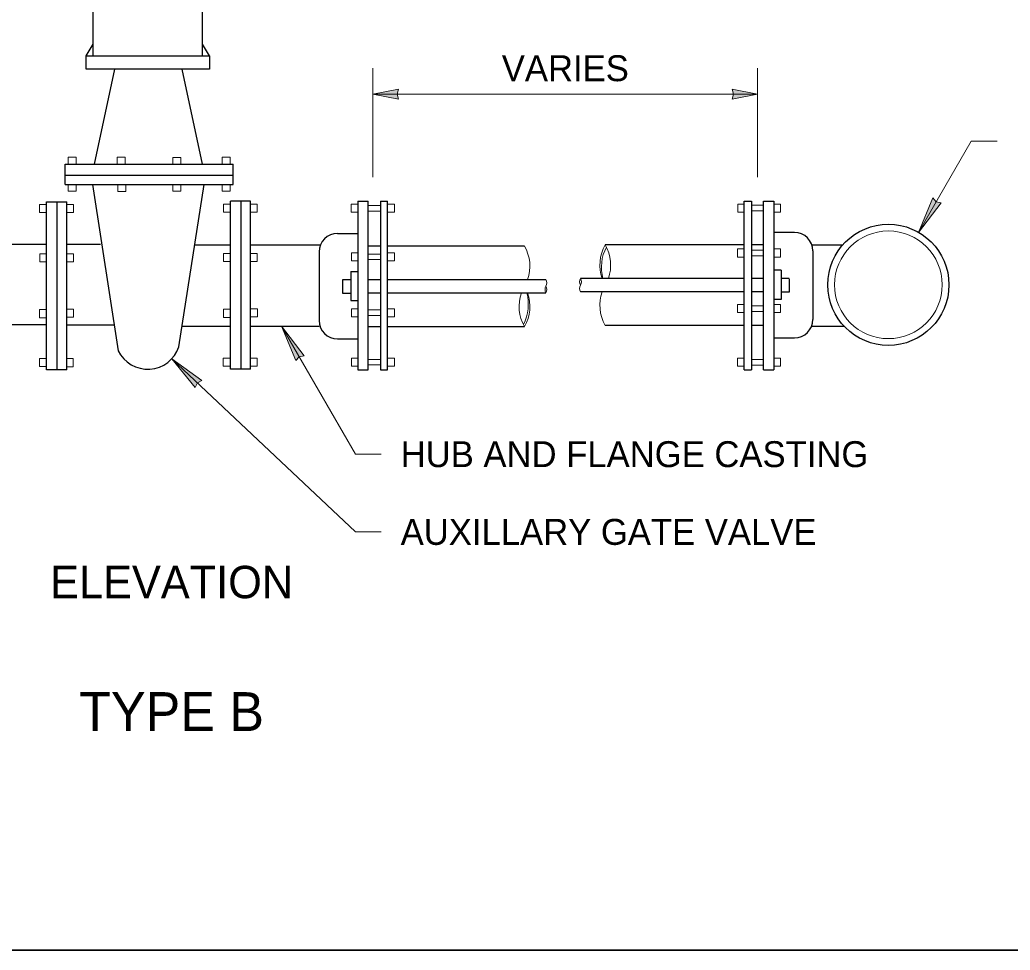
# Model space of a CAD drawing. Extents: x 99860 to 103153, y 99998 to 102077.
# Drawn here: x 101906 to 102518, y 100000 to 100574 of the extents above; entities that cross this region are included whole.
import ezdxf
from ezdxf.enums import TextEntityAlignment as Align

# ---------------------------------------------------------------- set-up
doc = ezdxf.new("R2010")
doc.units = 0
doc.header["$LTSCALE"] = 6.4
for name, color, linetype, lineweight in [('1', 7, 'Continuous', 25), ('15', 7, 'Continuous', 13), ('18', 7, 'Continuous', 13), ('20', 7, 'Continuous', 13), ('6', 7, 'Continuous', 25)]:
    doc.layers.add(name, color=color, linetype=linetype, lineweight=lineweight)

msp = doc.modelspace()

# ---------------------------------------------------------------- hatches: boundary and pattern name
at = {"layer": '15'}
for points in [[(102124.052, 100528.071), (102139.777, 100524.987), (102139.049, 100528.071), (102139.777, 100531.155)], [(102361.677, 100528.071), (102345.952, 100524.987), (102346.68, 100528.071), (102345.952, 100531.155)], [(102461.132, 100442.715), (102475.131, 100460.993), (102472.017, 100461.569), (102469.961, 100463.978)], [(102067.564, 100384.76), (102081.563, 100366.482), (102078.449, 100365.906), (102076.393, 100363.497)]]:
    msp.add_hatch(color=256, dxfattribs=at).paths.add_polyline_path(points)
at = {"layer": '20'}
msp.add_hatch(color=256, dxfattribs=at).paths.add_polyline_path([(101999.71, 100364.654), (102014.28, 100346.827), (102015.558, 100349.724), (102018.374, 100351.172)])

# ---------------------------------------------------------------- linework, layer by layer
at = {"layer": '1'}
msp.add_line((102018.714, 100484.735), (102006.202, 100543.535), dxfattribs=at)
at = {"layer": '1', "lineweight": 35}
msp.add_lwpolyline([(99862, 99999.5), (103151, 99999.5), (103151, 102075.5), (99862, 102075.5)], close=True, dxfattribs=at)
at = {"layer": '15'}
for p, q in [((102124.052, 100476.885), (102124.052, 100544.015)), ((102361.677, 100476.885), (102361.677, 100544.015)), ((102361.677, 100528.071), (102124.052, 100528.071)), ((102461.132, 100442.715), (102493.633, 100499.007)), ((102493.633, 100499.007), (102509.632, 100499.007)), ((102067.564, 100384.76), (102113.17, 100305.769)), ((102113.17, 100305.769), (102129.17, 100305.769)), ((102113.17, 100257.769), (102129.17, 100257.769))]:
    msp.add_line(p, q, dxfattribs=at)
for points in [[(102124.052, 100528.071), (102139.777, 100524.987), (102139.049, 100528.071), (102139.777, 100531.155)], [(102361.677, 100528.071), (102345.952, 100524.987), (102346.68, 100528.071), (102345.952, 100531.155)], [(102461.132, 100442.715), (102475.131, 100460.993), (102472.017, 100461.569), (102469.961, 100463.978)], [(102067.564, 100384.76), (102081.563, 100366.482), (102078.449, 100365.906), (102076.393, 100363.497)]]:
    msp.add_lwpolyline(points, close=True, dxfattribs=at)
at = {"layer": '18', "lineweight": 25}
for p, q in [((101951.214, 100551.772), (101951.214, 100607.085)), ((102018.777, 100551.772), (102018.777, 100607.085)), ((101946.964, 100551.772), (101951.214, 100558.985)), ((102023.039, 100551.772), (102018.777, 100558.985)), ((101952.052, 100484.735), (101964.577, 100543.535)), ((101933.914, 100484.735), (102037.652, 100484.735)), ((101933.914, 100472.247), (101933.914, 100484.735)), ((102037.652, 100472.247), (102037.652, 100484.735)), ((101933.914, 100478.097), (102037.652, 100478.097)), ((101933.914, 100472.247), (102037.652, 100472.247)), ((101950.727, 100472.247), (101966.664, 100369.622)), ((102004.139, 100372.022), (102019.677, 100472.247)), ((102035.952, 100358.147), (102035.952, 100461.885)), ((102048.452, 100461.885), (102035.952, 100461.885)), ((102042.589, 100358.147), (102042.589, 100461.885)), ((102048.452, 100358.147), (102048.452, 100461.885)), ((102114.777, 100461.885), (102114.777, 100357.772)), ((102114.777, 100461.885), (102121.152, 100461.885)), ((102121.152, 100357.935), (102121.152, 100461.885)), ((102128.614, 100461.885), (102128.614, 100357.935)), ((102128.614, 100461.885), (102133.127, 100461.885)), ((102133.127, 100357.935), (102133.127, 100461.885)), ((102353.389, 100357.935), (102353.389, 100461.885)), ((102353.389, 100461.885), (102357.889, 100461.885)), ((102357.889, 100461.885), (102357.889, 100357.935)), ((102365.352, 100357.935), (102365.352, 100461.885)), ((102365.352, 100461.885), (102371.739, 100461.885)), ((102371.739, 100461.885), (102371.739, 100357.935)), ((101922.389, 100357.935), (101922.389, 100461.66)), ((101922.389, 100461.66), (101934.877, 100461.66)), ((101929.014, 100357.935), (101929.014, 100461.66)), ((101934.877, 100357.935), (101934.877, 100461.66)), ((101897.077, 100435.397), (101922.389, 100435.397)), ((101934.877, 100435.397), (101955.752, 100435.397)), ((102013.906, 100435.022), (102035.952, 100435.022)), ((102376.202, 100419.297), (102371.739, 100419.297)), ((102376.202, 100419.297), (102376.202, 100401.322)), ((102105.277, 100413.585), (102110.302, 100413.585)), ((102105.277, 100413.41), (102105.277, 100405.147)), ((102110.302, 100418.647), (102110.302, 100400.672)), ((102110.302, 100418.647), (102114.777, 100418.647)), ((102121.152, 100413.585), (102128.614, 100413.585)), ((102133.127, 100413.585), (102230.907, 100413.585)), ((102353.389, 100414.21), (102252.233, 100414.21)), ((102365.352, 100414.21), (102357.889, 100414.21)), ((102381.227, 100414.21), (102376.202, 100414.21)), ((102381.227, 100414.047), (102381.227, 100405.785)), ((102105.277, 100405.147), (102110.302, 100405.147)), ((102110.302, 100400.672), (102114.777, 100400.672)), ((102121.152, 100405.36), (102128.614, 100405.36)), ((102133.127, 100405.36), (102230.908, 100405.36)), ((102353.389, 100406.01), (102252.219, 100406.01)), ((102365.352, 100406.01), (102357.889, 100406.01)), ((102376.202, 100401.322), (102371.739, 100401.322)), ((102381.227, 100405.785), (102376.202, 100405.785)), ((101922.389, 100385.622), (101826.888, 100385.622)), ((101934.877, 100385.622), (101964.18, 100385.622)), ((102006.114, 100384.76), (102035.952, 100384.76)), ((101934.877, 100357.935), (101922.389, 100357.935)), ((102048.452, 100358.147), (102035.952, 100358.147)), ((102353.389, 100357.935), (102357.889, 100357.935)), ((102365.352, 100357.935), (102371.739, 100357.935)), ((102114.777, 100357.772), (102121.152, 100357.772)), ((102128.614, 100357.772), (102133.127, 100357.772))]:
    msp.add_line(p, q, dxfattribs=at)
at = {"layer": '18'}
for p, q in [((101935.827, 100489.135), (101940.802, 100489.135)), ((101935.827, 100484.735), (101935.827, 100489.135)), ((101940.802, 100484.735), (101940.802, 100489.135)), ((101966.027, 100489.047), (101970.989, 100489.047)), ((101966.027, 100484.735), (101966.027, 100489.047)), ((101970.989, 100484.735), (101970.989, 100489.047)), ((102000.439, 100488.922), (102005.402, 100488.922)), ((102000.439, 100484.822), (102000.439, 100488.922)), ((102005.402, 100484.735), (102005.402, 100488.922)), ((102030.927, 100484.735), (102030.927, 100489.047)), ((102030.927, 100489.047), (102035.902, 100489.047)), ((102035.902, 100484.735), (102035.902, 100489.047)), ((101935.764, 100472.247), (101935.764, 100468.172)), ((101935.764, 100468.172), (101940.739, 100468.172)), ((101940.739, 100472.247), (101940.739, 100468.172)), ((101966.389, 100472.247), (101966.389, 100468.022)), ((101966.389, 100468.022), (101971.352, 100468.022)), ((101971.352, 100472.247), (101971.352, 100468.022)), ((102000.439, 100472.247), (102000.439, 100468.135)), ((102000.439, 100468.135), (102005.402, 100468.135)), ((102005.402, 100472.247), (102005.402, 100468.135)), ((102030.927, 100472.247), (102030.927, 100468.11)), ((102030.927, 100468.11), (102035.902, 100468.11)), ((102035.902, 100472.247), (102035.902, 100468.11)), ((101922.389, 100459.91), (101918.064, 100459.91)), ((101918.064, 100454.947), (101918.064, 100459.91)), ((101934.877, 100459.91), (101939.014, 100459.91)), ((101939.014, 100454.947), (101939.014, 100459.91)), ((102035.952, 100460.122), (102031.639, 100460.122)), ((102031.639, 100455.16), (102031.639, 100460.122)), ((102048.452, 100460.122), (102052.577, 100460.122)), ((102052.577, 100455.16), (102052.577, 100460.122)), ((102110.677, 100455.097), (102110.677, 100460.06)), ((102114.777, 100460.06), (102110.677, 100460.06)), ((102128.614, 100459.347), (102121.152, 100459.347)), ((102121.152, 100455.835), (102128.614, 100455.835)), ((102133.277, 100460.06), (102137.377, 100460.06)), ((102137.377, 100455.097), (102137.377, 100460.06)), ((102353.389, 100460.16), (102349.352, 100460.16)), ((102349.352, 100455.185), (102349.352, 100460.16)), ((102365.352, 100459.447), (102357.889, 100459.447)), ((102357.889, 100455.935), (102365.352, 100455.935)), ((102371.739, 100460.16), (102375.777, 100460.16)), ((102375.777, 100455.185), (102375.777, 100460.16)), ((101922.389, 100454.947), (101918.064, 100454.947)), ((101934.877, 100454.947), (101939.014, 100454.947)), ((102035.952, 100455.16), (102031.639, 100455.16)), ((102048.452, 100455.16), (102052.577, 100455.16)), ((102110.677, 100455.097), (102114.777, 100455.097)), ((102137.377, 100455.097), (102133.277, 100455.097)), ((102349.352, 100455.185), (102353.389, 100455.185)), ((102375.777, 100455.185), (102371.739, 100455.185)), ((102349.314, 100432.46), (102353.389, 100432.46)), ((102349.314, 100427.497), (102349.314, 100432.46)), ((102357.889, 100431.747), (102365.352, 100431.747)), ((102375.739, 100432.46), (102371.739, 100432.46)), ((102375.739, 100427.497), (102375.739, 100432.46)), ((101918.189, 100424.447), (101918.189, 100429.41)), ((101922.389, 100429.41), (101918.189, 100429.41)), ((101934.877, 100429.41), (101938.977, 100429.41)), ((101938.977, 100424.447), (101938.977, 100429.41)), ((102031.764, 100424.66), (102031.764, 100429.622)), ((102035.952, 100429.622), (102031.764, 100429.622)), ((102048.452, 100429.622), (102052.552, 100429.622)), ((102052.552, 100424.66), (102052.552, 100429.622)), ((102110.739, 100425.097), (102110.739, 100430.06)), ((102110.739, 100430.06), (102114.777, 100430.06)), ((102121.152, 100429.347), (102128.614, 100429.347)), ((102121.152, 100425.86), (102128.614, 100425.86)), ((102137.377, 100430.06), (102133.277, 100430.06)), ((102137.377, 100425.097), (102137.377, 100430.06)), ((102349.314, 100427.497), (102353.389, 100427.497)), ((102357.889, 100428.272), (102365.352, 100428.272)), ((102375.739, 100427.497), (102371.739, 100427.497)), ((101922.289, 100424.447), (101918.189, 100424.447)), ((101934.877, 100424.447), (101938.977, 100424.447)), ((102035.864, 100424.66), (102031.764, 100424.66)), ((102048.452, 100424.66), (102052.552, 100424.66)), ((102110.739, 100425.097), (102114.777, 100425.097)), ((102137.377, 100425.097), (102133.277, 100425.097)), ((101918.064, 100390.035), (101918.064, 100394.997)), ((101922.389, 100394.997), (101918.064, 100394.997)), ((101934.877, 100395.372), (101939.102, 100395.372)), ((101939.102, 100390.397), (101939.102, 100395.372)), ((102031.639, 100390.247), (102031.639, 100395.21)), ((102035.952, 100395.21), (102031.639, 100395.21)), ((102048.452, 100395.585), (102052.677, 100395.585)), ((102052.677, 100390.622), (102052.677, 100395.585)), ((102110.739, 100390.56), (102110.739, 100395.522)), ((102114.777, 100395.522), (102110.739, 100395.522)), ((102128.614, 100394.81), (102121.152, 100394.81)), ((102133.127, 100395.522), (102137.414, 100395.522)), ((102137.414, 100390.56), (102137.414, 100395.522)), ((102353.389, 100398.11), (102349.252, 100398.11)), ((102349.252, 100393.147), (102349.252, 100398.11)), ((102365.352, 100397.397), (102357.889, 100397.397)), ((102371.739, 100398.11), (102375.739, 100398.11)), ((102375.739, 100393.147), (102375.739, 100398.11)), ((101922.389, 100390.035), (101918.064, 100390.035)), ((101934.877, 100390.397), (101939.102, 100390.397)), ((102035.952, 100390.247), (102031.639, 100390.247)), ((102048.452, 100390.622), (102052.677, 100390.622)), ((102110.739, 100390.56), (102114.777, 100390.56)), ((102121.152, 100391.297), (102128.614, 100391.297)), ((102137.414, 100390.56), (102133.127, 100390.56)), ((102349.252, 100393.147), (102353.389, 100393.147)), ((102357.889, 100393.885), (102365.352, 100393.885)), ((102375.739, 100393.147), (102371.739, 100393.147)), ((101917.977, 100359.847), (101917.977, 100364.81)), ((101922.389, 100364.81), (101917.977, 100364.81)), ((101934.877, 100364.747), (101938.952, 100364.747)), ((101938.952, 100359.785), (101938.952, 100364.747)), ((102031.552, 100360.06), (102031.552, 100365.022)), ((102035.952, 100365.022), (102031.552, 100365.022)), ((102048.452, 100364.96), (102052.514, 100364.96)), ((102052.514, 100359.997), (102052.514, 100364.96)), ((102110.739, 100360.06), (102110.739, 100365.022)), ((102110.739, 100365.022), (102114.777, 100365.022)), ((102121.152, 100364.285), (102128.614, 100364.285)), ((102137.414, 100365.022), (102133.127, 100365.022)), ((102137.414, 100360.06), (102137.414, 100365.022)), ((102349.252, 100364.997), (102353.389, 100364.997)), ((102349.252, 100360.022), (102349.252, 100364.997)), ((102357.889, 100364.285), (102365.352, 100364.285)), ((102375.739, 100364.997), (102371.739, 100364.997)), ((102375.739, 100360.022), (102375.739, 100364.997)), ((101922.389, 100359.847), (101917.977, 100359.847)), ((101934.877, 100359.785), (101938.952, 100359.785)), ((102035.952, 100360.06), (102031.552, 100360.06)), ((102048.452, 100359.997), (102052.514, 100359.997)), ((102110.739, 100360.06), (102114.777, 100360.06)), ((102121.152, 100360.835), (102128.614, 100360.835)), ((102137.414, 100360.06), (102133.127, 100360.06)), ((102349.252, 100360.022), (102353.389, 100360.022)), ((102357.889, 100360.797), (102365.352, 100360.797)), ((102375.739, 100360.022), (102371.739, 100360.022))]:
    msp.add_line(p, q, dxfattribs=at)
at = {"layer": '18', "lineweight": 25}
msp.add_lwpolyline([(101946.964, 100543.535), (101946.964, 100551.772), (102023.039, 100551.772), (102023.039, 100543.535)], close=True, dxfattribs=at)
at = {"layer": '18'}
for centre, start, end in [((102227.347, 100411.528), 330, 30), ((102255.78, 100412.178), 150, 210), ((102248.657, 100412.178), 330, 30), ((102234.47, 100407.416), 150, 210), ((102227.347, 100407.416), 330, 30), ((102255.78, 100408.066), 150, 210)]:
    msp.add_arc(centre, 4.112, start, end, dxfattribs=at)
at = {"layer": '18', "lineweight": 25}
msp.add_arc((101984.906, 100378.6), 20.339, 206.05486, 341.14368, dxfattribs=at)
at = {"layer": '20'}
msp.add_line((101999.71, 100364.654), (102113.17, 100257.769), dxfattribs=at)
msp.add_lwpolyline([(101999.71, 100364.654), (102014.28, 100346.827), (102015.558, 100349.724), (102018.374, 100351.172)], close=True, dxfattribs=at)
at = {"layer": '6'}
for p, q in [((102102.164, 100442.022), (102114.777, 100442.022)), ((102384.377, 100442.672), (102371.739, 100442.672)), ((102048.452, 100435.022), (102091.677, 100435.022)), ((102121.152, 100434.31), (102128.614, 100434.31)), ((102133.127, 100434.31), (102217.62, 100434.31)), ((102353.389, 100434.96), (102267.516, 100434.96)), ((102365.352, 100434.96), (102357.889, 100434.96)), ((102395.102, 100435.022), (102414.352, 100435.022)), ((102395.727, 100431.322), (102395.727, 100388.86)), ((102090.814, 100430.672), (102090.814, 100388.21)), ((102048.452, 100384.76), (102090.814, 100384.76)), ((102121.152, 100384.572), (102128.614, 100384.572)), ((102133.127, 100384.572), (102217.642, 100384.572)), ((102353.389, 100385.222), (102267.538, 100385.222)), ((102365.352, 100385.222), (102357.889, 100385.222)), ((102394.952, 100384.76), (102415.152, 100384.76)), ((102114.777, 100376.86), (102102.164, 100376.86)), ((102371.739, 100377.51), (102384.377, 100377.51))]:
    msp.add_line(p, q, dxfattribs=at)
msp.add_circle((102442.432, 100410.325), 37.401, dxfattribs=at)
at = {"layer": '6', "lineweight": 13}
msp.add_circle((102442.432, 100410.325), 33.245, dxfattribs=at)
at = {"layer": '6'}
for centre, start, end in [((102102.152, 100430.674), 90, 180), ((102384.392, 100431.312), 0, 90), ((102384.392, 100388.865), 270, 0), ((102102.152, 100388.226), 180, 270)]:
    msp.add_arc(centre, 11.348, start, end, dxfattribs=at)
at = {"layer": '6', "lineweight": 13}
for centre, radius, start, end in [((102196.121, 100421.847), 24.85, 340.5797, 30), ((102289.059, 100422.497), 24.85, 150, 199.48143), ((102292.017, 100421.159), 26.841, 152.35096, 195.00633), ((102246.017, 100422.497), 24.85, 340.51857, 30), ((102239.163, 100396.997), 24.85, 160.488, 210), ((102193.102, 100398.369), 26.91, 332.34757, 15.05732), ((102196.121, 100396.997), 24.85, 330, 19.66493), ((102289.059, 100397.647), 24.85, 160.33507, 210)]:
    msp.add_arc(centre, radius, start, end, dxfattribs=at)

# ---------------------------------------------------------------- texts
at = {"layer": '20'}
for s, height, p in [('VARIES', 16, (102242.866, 100536.071)), ('ELEVATION', 20, (101999.672, 100216.818)), ('TYPE B', 24, (101999.673, 100134.818))]:
    msp.add_text(s, height=height, dxfattribs=at).set_placement(p, align=Align.CENTER)
for s, p in [('HUB AND FLANGE CASTING', (102141.17, 100297.769)), ('AUXILLARY GATE VALVE', (102141.17, 100249.769))]:
    msp.add_text(s, height=16, dxfattribs=at).set_placement(p)

doc.saveas('drawing.dxf')
